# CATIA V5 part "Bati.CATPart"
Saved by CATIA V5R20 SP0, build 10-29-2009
Part number: Bati
Bounding box of the stored display mesh (mm): x 0 to 300, y 0 to 500, z -231.075 to -31.075
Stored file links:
  D:\Dropbox\IAO_2011\MMS_GR1\abruchon\abruchon\Bati.CATPart
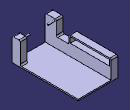
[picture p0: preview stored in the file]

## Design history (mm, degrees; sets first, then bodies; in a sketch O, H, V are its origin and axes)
Body1 (main body)
  Sketch1 on yz-plane, origin (0, 0, 0), H (0, 1, 0), V (0, 0, 1)
    line L1 (0, -231.0754) -> (500, -231.0754)
    point P1 (0, -231.0754)
    line L2 (500, -231.0754) -> (500, -81.0754)
    line L3 (500, -81.0754) -> (180, -81.0754)
    line L4 (0, -231.0754) -> (0, -31.0754)
    line L5 (0, -31.0754) -> (85, -31.0754)
    line L6 (85, -31.0754) -> (85, -144.0754)
    line L7 (85, -144.0754) -> (180, -144.0754)
    line L8 (180, -144.0754) -> (180, -81.0754)
    line L9 (190, -91.0754) -> (490, -91.0754)
    line L10 (490, -91.0754) -> (490, -134.0754)
    line L11 (490, -134.0754) -> (190, -134.0754)
    line L12 (190, -134.0754) -> (190, -91.0754)
    length L1 = 500
    length L2 = 150
    length L3 = 320
    length L4 = 200
    distance L10 L2 = 10
    distance L9 L3 = 10
    length L12 = 43
    distance L12 L8 = 10
    distance L7 L11 = 10
    coincidence: P1 V
    horizontal: L1 H, L3 H, L5 H, L7 H, L9 H, L11 H
    vertical: L2 V, L4 V, L6 V, L8 V, L10 V, L12 V
  Pad1: profile Sketch1, direction (1, 0, 0), length 50
  Sketch2 on end face of Pad1, origin (50, 0, 0), H (0, 1, 0), V (0, 0, 1)
    line L1 (0, -221.0754) -> (500, -221.0754)
    line L2 (500, -221.0754) -> (500, -231.0754)
    line L3 (500, -231.0754) -> (0, -231.0754)
    line L4 (0, -231.0754) -> (0, -221.0754)
    reference projected line E1 (0, -231.0754) -> (500, -231.0754) from edge [face of Pad1 from Sketch1.L1 | end face of Pad1]
    reference projected line E2 (0, -31.0754) -> (0, -231.0754) from edge [face of Pad1 from Sketch1.L4 | end face of Pad1]
    reference projected line E3 (500, -231.0754) -> (500, -81.0754) from edge [face of Pad1 from Sketch1.L2 | end face of Pad1]
    distance L3 E1 = 0
    distance L4 E2 = 0
    distance L2 E3 = 0
    length L4 = 10
    horizontal: L1 H, L3 H
    vertical: L2 V, L4 V
  Pad2: profile Sketch2, direction (1, 0, 0), length 200
  Sketch3 on end face of Pad2, origin (250, 0, 0), H (0, 1, 0), V (0, 0, 1)
    point P1 (0, -57.1322)
    line L1 (0, -57.1322) -> (59.8463, -57.1322)
    line L2 (0, -231.0754) -> (0, -57.1322)
    line L3 (59.8463, -221.0754) -> (500, -221.0754)
    line L4 (500, -221.0754) -> (500, -231.0754)
    line L5 (59.8463, -57.1322) -> (59.8463, -221.0754)
    line L6 (500, -231.0754) -> (0, -231.0754)
    reference projected line E1 (500, -221.0754) -> (0, -221.0754) from edge [face of Pad2 from Sketch2.L1 | end face of Pad2]
    reference projected line E2 (500, -231.0754) -> (500, -221.0754) from edge [face of Pad2 | end face of Pad2]
    reference projected line E3 (0, -231.0754) -> (500, -231.0754) from edge [face of Pad2 | end face of Pad2]
    distance E1 L3 = 0
    distance L4 E2 = 0
    distance L6 E3 = 0
    coincidence: P1 V
    horizontal: L1 H, L3 H, L6 H
    vertical: L2 V, L4 V, L5 V
  Pad3: profile Sketch3, direction (1, 0, 0), length 50
  Fillet1: radius 10, on edge [face of Pad1 from Sketch1.L3 | face of Pad2]
  Fillet2: radius 10, on edge [face of Pad1 from Sketch1.L8 | face of Pad1 from Sketch1.L3]
  Fillet3: radius 10, on edge [face of Pad1 from Sketch1.L7 | face of Pad1 from Sketch1.L8]
  Fillet4: radius 10, on edge [face of Pad1 from Sketch1.L6 | face of Pad1 from Sketch1.L7]
  Fillet5: radius 10, on edge [face of Pad1 from Sketch1.L5 | face of Pad1 from Sketch1.L6]
  Fillet6: radius 10, on edge [face of Pad3 | face of Pad1 from Sketch1.L5]
  Fillet7: radius 10, on edge [face of Pad3 from Sketch3.L1 | face of Pad3], deactivated
  Fillet8: radius 10, on edge [face of Pad3 | face of Pad3 from Sketch3.L1]
  Fillet9: radius 10, on edge [face of Pad3 from Sketch3.L1 | face of Pad3 from Sketch3.L5]
  Fillet10: radius 10, on edge [face of Pad3 from Sketch3.L5 | face of Pad3 from Sketch3.L3]
  Sketch4 on end face of Pad1, origin (50, 0, 0), H (0, 1, 0), V (0, 0, 1)
    circle A1 centre (70, -47.0754) radius 6
    point P1 (70, -47.0754)
    reference projected line E1 (0, -31.0754) -> (0, -231.0754) from edge [face of Pad3 | end face of Pad1]
    reference projected line E2 (85, -31.0754) -> (0, -31.0754) from edge [face of Pad1 from Sketch1.L5 | end face of Pad1]
    distance E1 P1 = 70
    distance P1 E2 = 16
  Pad4: profile Sketch4, direction (1, 0, 0), length 50
  Sketch5 on end face of Pad3, origin (300, 0, 0), H (0, 1, 0), V (0, 0, 1)
    circle A1 centre (30.3608, -80.7315) radius 6
    reference projected circle E1 centre (70, -47.0754) radius 6 from edge [face of Pad4 from Sketch4.A1 | end face of Pad4]
    distance A1 E1 = 40
  Pad5: profile Sketch5, direction (-1, 0, 0), length 100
